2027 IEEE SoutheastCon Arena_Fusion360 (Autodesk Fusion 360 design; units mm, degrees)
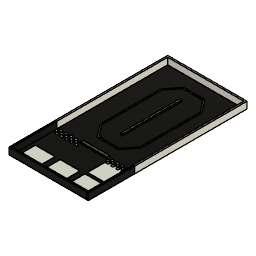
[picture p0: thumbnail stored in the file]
sketch "Sketch1" plane through (0, 0, 0) normal (0, 0, 1) x axis (1, 0, 0)
  line L1 (-609.6, 1219.2) -> (609.6, 1219.2)
  line L2 (-609.6, -1219.2) -> (-609.6, 1219.2)
  line L3 (609.6, -1219.2) -> (-609.6, -1219.2)
  line L4 (609.6, 1219.2) -> (609.6, -1219.2)
  line L5 (-609.6, -1219.2) -> (609.6, 1219.2)
  line L6 (609.6, -1219.2) -> (-609.6, 1219.2)
  point P6 (0, 0)
  point P1 (0, 0)
  point P3 (-609.6, 1219.2)
  point P4 (-609.6, -1219.2)
  point P2 (609.6, 1219.2)
  horizontal L1
  perpendicular L1 L2
  parallel L1 L3
  parallel L2 L4
  coincident L5 P6
  coincident L6 P6
  coincident P1 P6
  dimension "d1" distance P3 P4 = 2438.4
  dimension "d2" distance P2 P3 = 1219.2
extrude "Extrude1" new body sketch "Sketch1" profile of L1 L2 L3 L4 along normal blind 2
sketch "Sketch2" plane through (0, 0, 2) normal (0, 0, 1) x axis (-1, 0, 0)
  line L1 (-609.6, -1219.2) -> (-609.6, 1219.2)
  line L2 (609.6, -1219.2) -> (-609.6, -1219.2)
  line L3 (609.6, 1219.2) -> (609.6, -1219.2)
  line L4 (-609.6, 1219.2) -> (609.6, 1219.2)
  line L5 (0, -812.8) -> (0, -1193.8)
  line L6 (-0.1061, 101.6) -> (609.6, 101.6)
  line L7 (-12.7, -812.8) -> (0, -812.8)
  line L8 (12.7, -812.8) -> (0, -812.8)
  line L9 (-12.7, -812.8) -> (12.7, -812.8)
  line L10 (-12.7, 101.6) -> (-12.7, -812.8)
  line L11 (12.7, 101.6) -> (-12.7, 101.6)
  line L12 (12.7, -812.8) -> (12.7, 101.6)
  line L13 (584.2, -1219.2) -> (609.6, -1219.2)
  line L14 (584.2, 508) -> (584.2, -1193.8)
  line L15 (609.6, -1219.2) -> (609.6, 508)
  line L16 (-609.6, -1219.2) -> (609.6, -1219.2)
  line L17 (-609.6, -1193.8) -> (-609.6, -1219.2)
  line L18 (584.2, -1193.8) -> (-584.2, -1193.8)
  line L19 (609.6, -1219.2) -> (609.6, -1193.8)
  line L20 (-584.2, -1219.2) -> (-609.6, -1219.2)
  line L21 (-584.2, 508) -> (-584.2, -1193.8)
  line L22 (-609.6, 508) -> (-584.2, 508)
  line L23 (-609.6, -1219.2) -> (-609.6, 508)
  line L24 (0, -1016) -> (0, -812.8)
  line L25 (-0.1061, 314.8571) -> (-0.1061, 101.6)
  line L26 (0, -1022) -> (0, -1016)
  line L27 (0, -1010) -> (0, -1016)
  line L28 (0.008, 308.8579) -> (0.1061, 314.8571)
  line L29 (0.1075, 320.8571) -> (0.1061, 314.8571)
  line L30 (0, -1010) -> (0, -1022)
  line L31 (-298.8, -820.4626) -> (-298.9449, -820.4626)
  line L32 (609.6, 508) -> (584.2, 508)
  line L33 (293.9066, -819.0394) -> (316.7366, -819.0394)
  line L34 (293.9066, 111.7536) -> (293.9066, -819.0394)
  line L35 (316.7366, 111.7536) -> (293.9066, 111.7536)
  line L36 (316.7366, -819.0394) -> (316.7366, 111.7536)
  line L37 (-155.839, 285.9979) -> (-155.839, 308.8579)
  line L38 (155.855, 308.8579) -> (155.855, 285.9979)
  line L39 (-316.7286, -819.0333) -> (-293.8686, -819.0333)
  line L40 (-316.7286, 111.7597) -> (-316.7286, -819.0333)
  line L41 (-293.8686, 111.7597) -> (-316.7286, 111.7597)
  line L42 (-293.8686, -819.0333) -> (-293.8686, 111.7597)
  line L43 (-155.847, -1016.1376) -> (0, -1016.1376)
  line L44 (-155.847, -993.2776) -> (-155.847, -1016.1376)
  line L45 (0, -993.2776) -> (-155.847, -993.2776)
  line L46 (0, -1016.1376) -> (0, -993.2776)
  line L47 (155.847, -1016.1376) -> (0, -1016.1376)
  line L48 (155.847, -993.2776) -> (155.847, -1016.1376)
  line L49 (0, -993.2776) -> (155.847, -993.2776)
  line L50 (0, -1016.1376) -> (0, -993.2776)
  line L51 (155.847, -993.2776) -> (293.9066, -819.0394)
  line L52 (155.847, -1016.1376) -> (316.7366, -819.0394)
  line L53 (165.5003, -1016.1376) -> (316.7366, -819.0394)
  line L54 (155.847, -1016.1376) -> (165.5003, -1016.1376)
  line L55 (155.855, 285.9979) -> (293.9066, 111.7536)
  line L56 (155.855, 308.8579) -> (316.7366, 111.7536)
  line L57 (165.5083, 308.8579) -> (316.7366, 111.7536)
  line L58 (165.5083, 308.8579) -> (155.855, 308.8579)
  line L59 (-293.8686, 111.7597) -> (-155.839, 285.9979)
  line L60 (-316.7286, 111.7597) -> (-155.839, 308.8579)
  line L61 (-165.4923, 308.8579) -> (-316.7286, 111.7597)
  line L62 (-155.839, 308.8579) -> (-165.4923, 308.8579)
  line L63 (-155.847, -993.2776) -> (-293.8686, -819.0333)
  line L64 (-155.847, -1016.1376) -> (-316.7286, -819.0333)
  line L65 (-165.5003, -1016.1376) -> (-316.7286, -819.0333)
  line L66 (-155.847, -1016.1376) -> (-165.5003, -1016.1376)
  line L67 (-155.839, 308.8579) -> (0.008, 308.8579)
  line L68 (-155.839, 285.9979) -> (-155.839, 308.8579)
  line L69 (0.008, 285.9979) -> (-155.839, 285.9979)
  line L70 (0.008, 308.8579) -> (0.008, 285.9979)
  line L71 (155.855, 285.9979) -> (0.008, 285.9979)
  line L72 (155.855, 308.8579) -> (155.855, 285.9979)
  line L73 (0.008, 308.8579) -> (155.855, 308.8579)
  line L74 (0.008, 285.9979) -> (0.008, 308.8579)
  point P8 (609.6, 101.6)
  point P4 (609.6, -1219.2)
  point P14 (609.6, -1219.2)
  point P3 (-609.6, -1219.2)
  point P21 (-609.6, -1219.2)
  point P7 (0, -1016)
  point P27 (0, -1016)
  point P26 (-0.1061, 314.8571)
  point P29 (0.1061, 314.8571)
  point P28 (0, -1016)
  point P37 (0, -1193.8)
  point P48 (0, -1016.1376)
  point P6 (0, -812.8)
  point P10 (-12.7, -812.8)
  point P11 (12.7, -812.8)
  point P13 (12.7, 101.6)
  point P15 (584.2, -1219.2)
  point P17 (609.6, 508)
  point P18 (-609.6, -1219.2)
  point P20 (609.6, -1193.8)
  point P22 (-584.2, -1219.2)
  point P24 (-609.6, 508)
  point P25 (0, -1016)
  point P30 (0, -1022)
  point P31 (0, -1010)
  point P32 (0.008, 308.8579)
  point P33 (0.1075, 320.8571)
  point P39 (316.7366, -819.0394)
  point P40 (293.9066, -819.0394)
  point P42 (316.7366, 111.7536)
  point P43 (155.855, 285.9979)
  point P63 (155.855, 308.8579)
  point P44 (-293.8686, -819.0333)
  point P45 (-316.7286, -819.0333)
  point P49 (-155.847, -1016.1376)
  point P51 (0, -993.2776)
  point P52 (155.847, -1016.1376)
  point P54 (0, -993.2776)
  point P59 (-155.839, 308.8579)
  point P61 (0.008, 285.9979)
  point P62 (155.855, 285.9979)
  point P64 (0.008, 308.8579)
  point P55 (165.5003, -1016.1376)
  point P56 (165.5083, 308.8579)
  point P57 (-165.4923, 308.8579)
  point P58 (-165.5003, -1016.1376)
  point P46 (-316.7286, 111.7597)
  parallel L3 L5
  coincident L3 P8
  perpendicular L3 L6
  perpendicular L5 L7
  perpendicular L5 L8
  perpendicular L9 L10
  parallel L9 L11
  parallel L10 L12
  horizontal L13
  vertical L14
  vertical L15
  coincident P4 P14
  horizontal L16
  vertical L17
  horizontal L18
  vertical L19
  horizontal L20
  vertical L21
  horizontal L22
  vertical L23
  coincident P3 P21
  vertical L24
  vertical L25
  coincident P7 P27
  symmetric L24 P26 P29
  symmetric L24 P27 P28
  coincident L18 P37
  coincident L5 P7
  horizontal L33
  vertical L34
  horizontal L35
  vertical L36
  vertical L37
  vertical L38
  horizontal L39
  vertical L40
  horizontal L41
  vertical L42
  horizontal L43
  vertical L44
  horizontal L45
  vertical L46
  coincident L5 P48
  horizontal L47
  vertical L48
  horizontal L49
  vertical L50
  perpendicular L48 L54
  perpendicular L38 L58
  perpendicular L37 L62
  perpendicular L44 L66
  horizontal L67
  vertical L68
  horizontal L69
  vertical L70
  horizontal L71
  vertical L72
  horizontal L73
  vertical L74
  dimension "d6" distance L1 P7 = 609.6
  dimension "d9" distance P6 P10 = 12.7
  dimension "d10" distance P6 P11 = 12.7
  dimension "d11" distance P11 P13 = 914.4
  dimension "d12" distance P14 P15 = 25.4
  dimension "d13" distance P14 P17 = 1727.2
  dimension "d14" distance P14 P18 = 1219.2
  dimension "d15" distance P14 P20 = 25.4
  dimension "d16" distance P21 P22 = 25.4
  dimension "d17" distance P21 P24 = 1727.2
  dimension "d19" distance P6 P25 = 203.2
  dimension "d24" distance P27 P30 = 6
  dimension "d25" distance P28 P31 = 6
  dimension "d28" distance P29 P32 = 6
  dimension "d29" distance P29 P33 = 6
  dimension "d125" distance P39 P40 = 22.83
  dimension "d126" distance P39 P42 = 930.793
  dimension "d127" distance P43 P63 = 22.86
  dimension "d129" distance P44 P45 = 22.86
  dimension "d131" distance P48 P49 = 155.847
  dimension "d132" distance P48 P51 = 22.86
  dimension "d133" distance P48 P52 = 155.847
  dimension "d134" distance P48 P54 = 22.86
  dimension "d146" distance P32 P59 = 155.847
  dimension "d147" distance P32 P61 = 22.86
  dimension "d148" distance P61 P62 = 155.847
  dimension "d149" distance P61 P64 = 22.86
  dimension "d151" distance L11 L69 = 184.3979
  dimension "d152" distance P52 P55 = 9.6533
  dimension "d153" distance P56 P63 = 9.6533
  dimension "d154" distance P57 P59 = 9.6533
  dimension "d155" distance P49 P58 = 9.6533
  dimension "d156" distance P45 P46 = 930.793
  dimension "d157" distance P45 P58 = 248.4353
  dimension "d158" distance P39 P55 = 248.4353
  dimension "d159" distance P46 P57 = 248.4353
  dimension "d160" distance P42 P56 = 248.4353
  dimension "d161" distance L7 L18 = 381
extrude "Extrude2" add sketch "Sketch2" profile of L1 L2 L3 L9 L10 L11 L12 L13 L14 L15 L16 L17 L18 L19 L20 L21 L22 L23 L30 along normal blind 1
sketch "Sketch3" plane through (0, 0, 2) normal (0, 0, 1) x axis (-1, 0, 0)
  line L1 (609.6, 1219.2) -> (609.6, 508)
  line L2 (-609.6, 1219.2) -> (609.6, 1219.2)
  line L3 (-609.6, 508) -> (-609.6, 1219.2)
  line L4 (-584.2, 508) -> (-609.6, 508)
  line L5 (-584.2, -1193.8) -> (-584.2, 508)
  line L6 (584.2, -1193.8) -> (-584.2, -1193.8)
  line L7 (584.2, 508) -> (584.2, -1193.8)
  line L8 (203.2, 482.6) -> (584.2, 482.6)
  line L9 (203.2, 584.2) -> (203.2, 482.6)
  line L10 (584.2, 584.2) -> (203.2, 584.2)
  line L11 (584.2, 482.6) -> (584.2, 584.2)
  line L12 (-203.2, 482.6) -> (-584.2, 482.6)
  line L13 (-203.2, 584.2) -> (-203.2, 482.6)
  line L14 (-584.2, 584.2) -> (-203.2, 584.2)
  line L15 (-584.2, 482.6) -> (-584.2, 584.2)
  line L16 (-203.2, 482.6) -> (203.2, 482.6)
  line L17 (-203.2, 533.4) -> (-203.2, 482.6)
  line L18 (203.2, 533.4) -> (-203.2, 533.4)
  line L19 (203.2, 482.6) -> (203.2, 533.4)
  line L20 (584.2, 550.33) -> (584.2, 584.2)
  line L21 (584.2, 516.46) -> (584.2, 550.33)
  line L22 (584.2, 508) -> (584.2, 516.46)
  line L23 (203.2, 516.46) -> (584.2, 516.46)
  line L24 (203.2, 550.33) -> (584.2, 550.33)
  line L25 (546.1, 482.6) -> (584.2, 482.6)
  line L26 (522.9724, 482.6) -> (546.1, 482.6)
  line L27 (508, 482.6) -> (546.1, 482.6)
  line L28 (469.9, 482.6) -> (508, 482.6)
  line L29 (431.8, 482.6) -> (469.9, 482.6)
  line L30 (385, 482.6) -> (431.8, 482.6)
  line L31 (393.7, 482.6) -> (431.8, 482.6)
  line L32 (355.6, 482.6) -> (393.7, 482.6)
  line L33 (317.5, 482.6) -> (355.6, 482.6)
  line L34 (279.4, 482.6) -> (317.5, 482.6)
  line L35 (241.3, 482.6) -> (279.4, 482.6)
  line L36 (203.2, 482.6) -> (241.3, 482.6)
  line L37 (546.1, 584.2) -> (546.1, 482.6)
  line L38 (508, 584.2) -> (508, 482.6)
  line L39 (469.9, 584.2) -> (469.9, 482.6)
  line L40 (431.8, 584.2) -> (431.8, 482.6)
  line L41 (393.7, 584.2) -> (393.7, 482.6)
  line L42 (355.6, 584.2) -> (355.6, 482.6)
  line L43 (317.5, 584.2) -> (317.5, 482.6)
  line L44 (279.4, 584.2) -> (279.4, 482.6)
  line L45 (241.3, 584.2) -> (241.3, 482.6)
  line L46 (0, 973.0069) -> (0, 1219.2)
  line L47 (-584.2, 482.6) -> (-584.2, 584.2)
  line L48 (-203.2, 516.46) -> (-584.2, 516.46)
  line L49 (-203.2, 550.33) -> (-584.2, 550.33)
  line L50 (-584.2, 584.2) -> (-203.2, 584.2)
  line L51 (-546.1, 584.2) -> (-546.1, 482.6)
  line L52 (-203.2, 482.6) -> (-584.2, 482.6)
  line L53 (-508, 584.2) -> (-508, 482.6)
  line L54 (-469.9, 584.2) -> (-469.9, 482.6)
  line L55 (-393.7, 584.2) -> (-393.7, 482.6)
  line L56 (-431.8, 584.2) -> (-431.8, 482.6)
  line L57 (-355.6, 584.2) -> (-355.6, 482.6)
  line L58 (-317.5, 584.2) -> (-317.5, 482.6)
  line L59 (-279.4, 584.2) -> (-279.4, 482.6)
  line L60 (-241.3, 584.2) -> (-241.3, 482.6)
  line L61 (-203.2, 584.2) -> (-203.2, 482.6)
  line L62 (609.6, 508) -> (584.2, 508)
  line L63 (12.7, -812.8) -> (12.7, 101.6)
  line L64 (-12.7, -812.8) -> (12.7, -812.8)
  line L65 (-12.7, 101.6) -> (-12.7, -812.8)
  line L66 (12.7, 101.6) -> (-12.7, 101.6)
  line L67 (-155.847, -1016.1376) -> (155.847, -1016.1376)
  line L68 (-155.847, -993.2776) -> (-155.847, -1016.1376)
  line L69 (155.847, -993.2776) -> (-155.847, -993.2776)
  line L70 (155.847, -1016.1376) -> (155.847, -993.2776)
  point P19 (-203.2, 533.4)
  point P22 (584.2, 516.46)
  point P2 (584.2, 508)
  point P23 (584.2, 508)
  point P24 (203.2, 516.46)
  point P25 (203.2, 550.33)
  point P27 (522.9724, 482.6)
  point P31 (385, 482.6)
  point P33 (355.6, 482.6)
  point P35 (279.4, 482.6)
  point P36 (241.3, 482.6)
  point P37 (546.1, 584.2)
  point P38 (508, 584.2)
  point P39 (469.9, 584.2)
  point P40 (431.8, 584.2)
  point P41 (393.7, 584.2)
  point P42 (355.6, 584.2)
  point P43 (317.5, 584.2)
  point P44 (279.4, 584.2)
  point P45 (241.3, 584.2)
  point P46 (0, 1219.2)
  point P10 (584.2, 482.6)
  point P49 (-584.2, 482.6)
  point P11 (203.2, 482.6)
  point P57 (-203.2, 482.6)
  point P12 (203.2, 584.2)
  point P54 (-203.2, 584.2)
  point P13 (584.2, 584.2)
  point P48 (-584.2, 584.2)
  point P21 (584.2, 550.33)
  point P52 (-584.2, 550.33)
  point P50 (-584.2, 516.46)
  point P51 (-203.2, 516.46)
  point P53 (-203.2, 550.33)
  point P26 (546.1, 482.6)
  point P55 (-546.1, 482.6)
  point P28 (508, 482.6)
  point P58 (-508, 482.6)
  point P29 (469.9, 482.6)
  point P60 (-469.9, 482.6)
  point P30 (431.8, 482.6)
  point P64 (-431.8, 482.6)
  point P32 (393.7, 482.6)
  point P62 (-393.7, 482.6)
  point P66 (-355.6, 482.6)
  point P34 (317.5, 482.6)
  point P68 (-317.5, 482.6)
  point P70 (-279.4, 482.6)
  point P72 (-241.3, 482.6)
  point P56 (-546.1, 584.2)
  point P59 (-508, 584.2)
  point P61 (-469.9, 584.2)
  point P65 (-431.8, 584.2)
  point P63 (-393.7, 584.2)
  point P67 (-355.6, 584.2)
  point P69 (-317.5, 584.2)
  point P71 (-279.4, 584.2)
  point P73 (-241.3, 584.2)
  point P14 (-584.2, 482.6)
  point P15 (-203.2, 482.6)
  horizontal L8
  vertical L9
  horizontal L10
  vertical L11
  horizontal L12
  vertical L13
  horizontal L14
  vertical L15
  horizontal L16
  vertical L17
  horizontal L18
  vertical L19
  midpoint L13 P19
  vertical L20
  coincident L11 P22
  coincident P2 P23
  horizontal L23
  coincident L9 P24
  coincident L9 P25
  perpendicular L11 L25
  coincident L8 P27
  parallel L8 L27
  parallel L8 L28
  perpendicular L7 L29
  coincident L8 P31
  parallel L30 L31
  coincident L8 P33
  parallel L8 L33
  coincident L8 P35
  coincident L8 P36
  coincident L10 P37
  perpendicular L10 L37
  coincident L10 P38
  perpendicular L10 L38
  coincident L10 P39
  perpendicular L10 L39
  coincident L10 P40
  perpendicular L10 L40
  midpoint L10 P41
  coincident L10 P42
  perpendicular L10 L42
  coincident L10 P43
  perpendicular L10 L43
  coincident L10 P44
  perpendicular L10 L44
  coincident L10 P45
  perpendicular L10 L45
  midpoint L2 P46
  perpendicular L2 L46
  symmetric P10 L46 P49
  symmetric P11 L46 P57
  symmetric P12 L46 P54
  symmetric P13 L46 P48
  symmetric P21 L46 P52
  symmetric P22 L46 P50
  symmetric P24 L46 P51
  symmetric P25 L46 P53
  symmetric P26 L46 P55
  symmetric P28 L46 P58
  symmetric P29 L46 P60
  symmetric P30 L46 P64
  symmetric P32 L46 P62
  symmetric P33 L46 P66
  symmetric P34 L46 P68
  symmetric P35 L46 P70
  symmetric P36 L46 P72
  symmetric P37 L46 P56
  symmetric P38 L46 P59
  symmetric P39 L46 P61
  symmetric P40 L46 P65
  symmetric P41 L46 P63
  symmetric P42 L46 P67
  symmetric P43 L46 P69
  symmetric P44 L46 P71
  symmetric P45 L46 P73
  dimension "d41" distance P10 P11 = 381
  dimension "d43" distance P14 P15 = 381
  dimension "d45" distance P13 P21 = 33.87
  dimension "d46" distance P21 P22 = 33.87
  dimension "d47" angle L23 L24 = 180
  dimension "d48" distance P10 P26 = 38.1
  dimension "d49" distance P26 P28 = 38.1
  dimension "d50" distance P28 P29 = 38.1
  dimension "d51" distance P29 P30 = 38.1
  dimension "d52" distance P30 P32 = 38.1
  dimension "d53" distance P32 P33 = 38.1
  dimension "d54" distance P33 P34 = 38.1
  dimension "d55" distance P34 P35 = 38.1
  dimension "d56" distance P35 P36 = 38.1
extrude "Extrude3" new body sketch "Sketch3" profile of L8 L9 L10 L11 L12 L13 L14 L15 L17 L19 L23 L24 L37 L38 L39 L40 L41 L42 L43 L44 L45 L47 L48 L49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 along normal blind 0.2
sketch "Sketch4" plane through (0, 0, 2) normal (0, 0, 1) x axis (-1, 0, 0)
  line L1 (609.6, 1219.2) -> (609.6, 508)
  line L2 (-609.6, 1219.2) -> (609.6, 1219.2)
  line L3 (-609.6, 508) -> (-609.6, 1219.2)
  line L4 (-584.2, 508) -> (-609.6, 508)
  line L5 (-584.2, -1193.8) -> (-584.2, 508)
  line L6 (584.2, -1193.8) -> (-584.2, -1193.8)
  line L7 (584.2, 508) -> (584.2, -1193.8)
  line L8 (-202.6624, 508.0325) -> (202.5451, 508.0325)
  line L9 (-202.6624, 546.6239) -> (-202.6624, 508.0325)
  line L10 (202.5451, 546.6239) -> (-202.6624, 546.6239)
  line L11 (202.5451, 508.0325) -> (202.5451, 546.6239)
  line L12 (609.6, 508) -> (584.2, 508)
  line L13 (12.7, -812.8) -> (12.7, 101.6)
  line L14 (-12.7, -812.8) -> (12.7, -812.8)
  line L15 (-12.7, 101.6) -> (-12.7, -812.8)
  line L16 (12.7, 101.6) -> (-12.7, 101.6)
  line L17 (-155.847, -1016.1376) -> (155.847, -1016.1376)
  line L18 (-155.847, -993.2776) -> (-155.847, -1016.1376)
  line L19 (155.847, -993.2776) -> (-155.847, -993.2776)
  line L20 (155.847, -1016.1376) -> (155.847, -993.2776)
  horizontal L8
  vertical L9
  horizontal L10
  vertical L11
sketch "Sketch5" plane through (0, 0, 2) normal (0, 0, 1) x axis (-1, 0, 0)
  line L1 (609.6, 1219.2) -> (609.6, 508)
  line L2 (-609.6, 1219.2) -> (609.6, 1219.2)
  line L3 (-609.6, 508) -> (-609.6, 1219.2)
  line L4 (-584.2, 508) -> (-609.6, 508)
  line L5 (-584.2, -1193.8) -> (-584.2, 508)
  line L6 (584.2, -1193.8) -> (-584.2, -1193.8)
  line L7 (584.2, 508) -> (584.2, -1193.8)
  line L8 (-609.6, 546.6239) -> (-202.6624, 546.6239)
  line L9 (609.6, 558.7999) -> (-609.6, 558.7999)
  line L10 (-609.6, 508) -> (-609.6, 1219.2)
  line L11 (-533.4, 558.7999) -> (-533.4, 1219.2)
  line L12 (-228.6, 558.7999) -> (-533.4, 558.7999)
  line L13 (-228.6, 863.5999) -> (-228.6, 558.7999)
  line L14 (-533.4, 863.5999) -> (-228.6, 863.5999)
  line L15 (-533.4, 558.7999) -> (-533.4, 863.5999)
  line L16 (609.6, 863.5999) -> (-609.6, 863.5999)
  line L17 (609.6, 888.9999) -> (-609.6, 888.9999)
  line L18 (-228.6, 888.9999) -> (-533.4, 888.9999)
  line L19 (-228.6, 1193.7999) -> (-228.6, 888.9999)
  line L20 (-533.4, 1193.7999) -> (-228.6, 1193.7999)
  line L21 (-533.4, 888.9999) -> (-533.4, 1193.7999)
  line L22 (-241.3, 507.1408) -> (-241.3, 1219.2)
  line L23 (-152.4, 546.6239) -> (-152.4, 1219.2)
  line L24 (152.4, 888.9999) -> (-152.4, 888.9999)
  line L25 (152.4, 1193.7999) -> (152.4, 888.9999)
  line L26 (-152.4, 1193.7999) -> (152.4, 1193.7999)
  line L27 (-152.4, 888.9999) -> (-152.4, 1193.7999)
  line L28 (228.6, 508.0325) -> (228.6, 1219.2)
  line L29 (533.4, 888.9999) -> (228.6, 888.9999)
  line L30 (533.4, 1193.7999) -> (533.4, 888.9999)
  line L31 (228.6, 1193.7999) -> (533.4, 1193.7999)
  line L32 (228.6, 888.9999) -> (228.6, 1193.7999)
  line L33 (609.6, 508) -> (584.2, 508)
  line L34 (12.7, -812.8) -> (12.7, 101.6)
  line L35 (-12.7, -812.8) -> (12.7, -812.8)
  line L36 (-12.7, 101.6) -> (-12.7, -812.8)
  line L37 (12.7, 101.6) -> (-12.7, 101.6)
  line L38 (-155.847, -1016.1376) -> (155.847, -1016.1376)
  line L39 (-155.847, -993.2776) -> (-155.847, -1016.1376)
  line L40 (155.847, -993.2776) -> (-155.847, -993.2776)
  line L41 (155.847, -1016.1376) -> (155.847, -993.2776)
  point P11 (-609.6, 546.6239)
  point P12 (-609.6, 558.7999)
  point P13 (609.6, 558.7999)
  point P5 (-609.6, 1219.2)
  point P14 (-609.6, 1219.2)
  point P6 (-609.6, 508)
  point P15 (-609.6, 508)
  point P16 (-533.4, 1219.2)
  point P17 (-533.4, 558.7999)
  point P21 (-609.6, 863.5999)
  point P22 (609.6, 863.5999)
  point P23 (-609.6, 888.9999)
  point P24 (609.6, 888.9999)
  point P25 (-533.4, 888.9999)
  point P29 (-241.3, 1219.2)
  point P31 (-152.4, 1219.2)
  point P33 (-152.4, 888.9999)
  point P37 (228.6, 1219.2)
  point P39 (228.6, 888.9999)
  point P18 (-228.6, 558.7999)
  point P20 (-533.4, 863.5999)
  point P26 (-228.6, 888.9999)
  point P28 (-533.4, 1193.7999)
  point P34 (152.4, 888.9999)
  point P36 (-152.4, 1193.7999)
  point P40 (533.4, 888.9999)
  point P42 (228.6, 1193.7999)
  coincident L3 P11
  perpendicular L3 L8
  coincident L3 P12
  perpendicular L3 L9
  coincident L1 P13
  coincident P5 P14
  coincident P6 P15
  coincident L2 P16
  coincident L9 P17
  horizontal L12
  vertical L13
  horizontal L14
  vertical L15
  horizontal L16
  coincident L10 P21
  coincident L1 P22
  coincident L10 P23
  coincident L1 P24
  horizontal L18
  vertical L19
  horizontal L20
  vertical L21
  coincident L11 P25
  coincident L17 P25
  coincident L2 P29
  perpendicular L8 L22
  vertical L23
  coincident L2 P31
  horizontal L24
  vertical L25
  horizontal L26
  vertical L27
  coincident L23 P33
  coincident L17 P33
  coincident L2 P37
  horizontal L29
  vertical L30
  horizontal L31
  vertical L32
  coincident L28 P39
  coincident L17 P39
  collinear L14 L16
  dimension "d61" distance L8 L9 = 12.176
  dimension "d62" angle L10 L11 = 180
  dimension "d63" distance L10 L11 = 76.2
  dimension "d64" distance P17 P18 = 304.8
  dimension "d65" distance P17 P20 = 304.8
  dimension "d66" angle L16 L17 = 180
  dimension "d67" distance L16 L17 = 25.4
  dimension "d68" distance P25 P26 = 304.8
  dimension "d69" distance P25 P28 = 304.8
  dimension "d73" distance P33 P34 = 304.8
  dimension "d74" distance P33 P36 = 304.8
  dimension "d76" distance P39 P40 = 304.8
  dimension "d77" distance P39 P42 = 304.8
  dimension "d141" distance L25 L32 = 76.2
  dimension "d144" distance L19 L23 = 76.2
  dimension "d145" distance L1 L30 = 76.2
extrude "Extrude5" new body sketch "Sketch5" profile of L18 L19 L20 L21 L24 L25 L26 L27 L29 L30 L31 L32 along normal blind 0.1
sketch "Sketch6" plane through (0, 0, 2) normal (0, 0, 1) x axis (-1, 0, 0)
  line L1 (609.6, 1219.2) -> (609.6, 508)
  line L2 (-609.6, 1219.2) -> (609.6, 1219.2)
  line L3 (-609.6, 508) -> (-609.6, 1219.2)
  line L4 (-584.2, 508) -> (-609.6, 508)
  line L5 (-584.2, -1193.8) -> (-584.2, 508)
  line L6 (584.2, -1193.8) -> (-584.2, -1193.8)
  line L7 (584.2, 508) -> (584.2, -1193.8)
  line L8 (-228.6, 507.1408) -> (-228.6, 1219.2)
  line L9 (609.6, 572.0239) -> (-609.6, 572.0239)
  line L10 (-533.4, 572.0239) -> (-533.4, 1219.2)
  line L11 (-533.4, 876.8239) -> (-228.6, 876.8239)
  line L12 (-533.4, 572.0239) -> (-228.6, 572.0239)
  line L13 (-533.4, 876.8239) -> (-533.4, 572.0239)
  line L14 (-228.6, 572.0239) -> (-228.6, 876.8239)
  line L15 (609.6, 508) -> (584.2, 508)
  line L16 (12.7, -812.8) -> (12.7, 101.6)
  line L17 (-12.7, -812.8) -> (12.7, -812.8)
  line L18 (-12.7, 101.6) -> (-12.7, -812.8)
  line L19 (12.7, 101.6) -> (-12.7, 101.6)
  line L20 (-155.847, -1016.1376) -> (155.847, -1016.1376)
  line L21 (-155.847, -993.2776) -> (-155.847, -1016.1376)
  line L22 (155.847, -993.2776) -> (-155.847, -993.2776)
  line L23 (155.847, -1016.1376) -> (155.847, -993.2776)
  point P11 (-533.4, 572.0239)
  point P18 (-228.6, 572.0239)
  point P17 (-533.4, 876.8239)
  coincident P11 L9
  horizontal L11
  coincident L8 P18
  coincident L9 P18
  perpendicular L10 L12
  perpendicular L11 L13
  perpendicular L9 L14
  dimension "d80" distance P11 P17 = 304.8
extrude "Extrude6" new body sketch "Sketch6" profile of L11 L12 L13 L14 along normal blind 0.3
extrude "Extrude7" add of existing geometry blind 101.6
extrude "Extrude8" add of existing geometry blind 25.4
extrude "Extrude9" new body of existing geometry blind 25.4
sketch "Sketch7" plane through (0, 0, 2.3) normal (0, 0, 1) x axis (-1, 0, 0)
  dimension "d89" = 40
sketch "Sketch12" plane through (0, 0, 2) normal (0, 0, 1) x axis (-1, 0, 0)
  line L1 (-584.2, -1193.8) -> (-584.2, 508)
  line L2 (584.2, -1193.8) -> (-584.2, -1193.8)
  line L3 (584.2, 508) -> (584.2, -1193.8)
  line L4 (609.6, 508) -> (584.2, 508)
  line L5 (609.6, 1219.2) -> (609.6, 508)
  line L6 (-609.6, 1219.2) -> (609.6, 1219.2)
  line L7 (-609.6, 508) -> (-609.6, 1219.2)
  line L8 (-584.2, 508) -> (-609.6, 508)
  line L9 (584.3158, 508) -> (609.6, 508)
  line L10 (584.3158, 1219.2) -> (584.3158, 508)
  line L11 (609.6, 1219.2) -> (584.3158, 1219.2)
  line L12 (609.6, 508) -> (609.6, 1219.2)
  line L13 (-609.6, 508) -> (-584.2, 508)
  line L14 (-609.6, 1219.2) -> (-609.6, 508)
  line L15 (-584.2, 1219.2) -> (-609.6, 1219.2)
  line L16 (-584.2, 508) -> (-584.2, 1219.2)
  line L17 (-584.0842, 1219.2) -> (584.3158, 1219.2)
  line L18 (-584.0842, 1193.8) -> (-584.0842, 1219.2)
  line L19 (584.3158, 1193.8) -> (-584.0842, 1193.8)
  line L20 (584.3158, 1219.2) -> (584.3158, 1193.8)
  line L21 (12.7, -812.8) -> (12.7, 101.6)
  line L22 (-12.7, -812.8) -> (12.7, -812.8)
  line L23 (-12.7, 101.6) -> (-12.7, -812.8)
  line L24 (12.7, 101.6) -> (-12.7, 101.6)
  line L25 (-155.847, -1016.1376) -> (155.847, -1016.1376)
  line L26 (-155.847, -993.2776) -> (-155.847, -1016.1376)
  line L27 (155.847, -993.2776) -> (-155.847, -993.2776)
  line L28 (155.847, -1016.1376) -> (155.847, -993.2776)
  point P12 (584.3158, 1219.2)
  point P6 (609.6, 508)
  point P10 (609.6, 508)
  point P8 (-609.6, 1219.2)
  point P16 (-609.6, 1219.2)
  point P2 (-584.2, 508)
  point P14 (-584.2, 508)
  point P20 (584.3158, 1193.8)
  point P19 (-584.0842, 1193.8)
  horizontal L9
  vertical L10
  horizontal L11
  vertical L12
  coincident L6 P12
  coincident P6 P10
  horizontal L13
  vertical L14
  horizontal L15
  vertical L16
  coincident P8 P16
  coincident P2 P14
  horizontal L17
  vertical L18
  horizontal L19
  vertical L20
  dimension "d119" distance P12 P20 = 25.4
  dimension "d120" distance P19 P20 = 1168.4
extrude "Extrude10" new body sketch "Sketch12" profile of L4 L5 L6 L7 L8 L9 L10 L11 L12 L13 L14 L15 L16 L17 L18 L19 L20 along normal blind 101.6
derived_base_feature "Derived Base Feature" bodies "Body1 (1)"
remove_body "RemoveBody7"
extrude "Extrude11" new body sketch "Sketch2" profile of L30 L33 L34 L35 L36 L37 L38 L39 L40 L41 L42 L43 L44 L45 L46 L47 L48 L49 L50 L51 L52 L53 L54 L55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 along normal blind 0.1
extrude "Extrude12" add of existing geometry blind 0.1
extrude "Extrude13" add sketch "Sketch5" profile of L18 L19 L20 L21 L24 L25 L26 L27 L29 L30 L31 L32 along normal blind 0.1
move "Move1"
move "Move2"
named bodies: "Body1 (1)"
